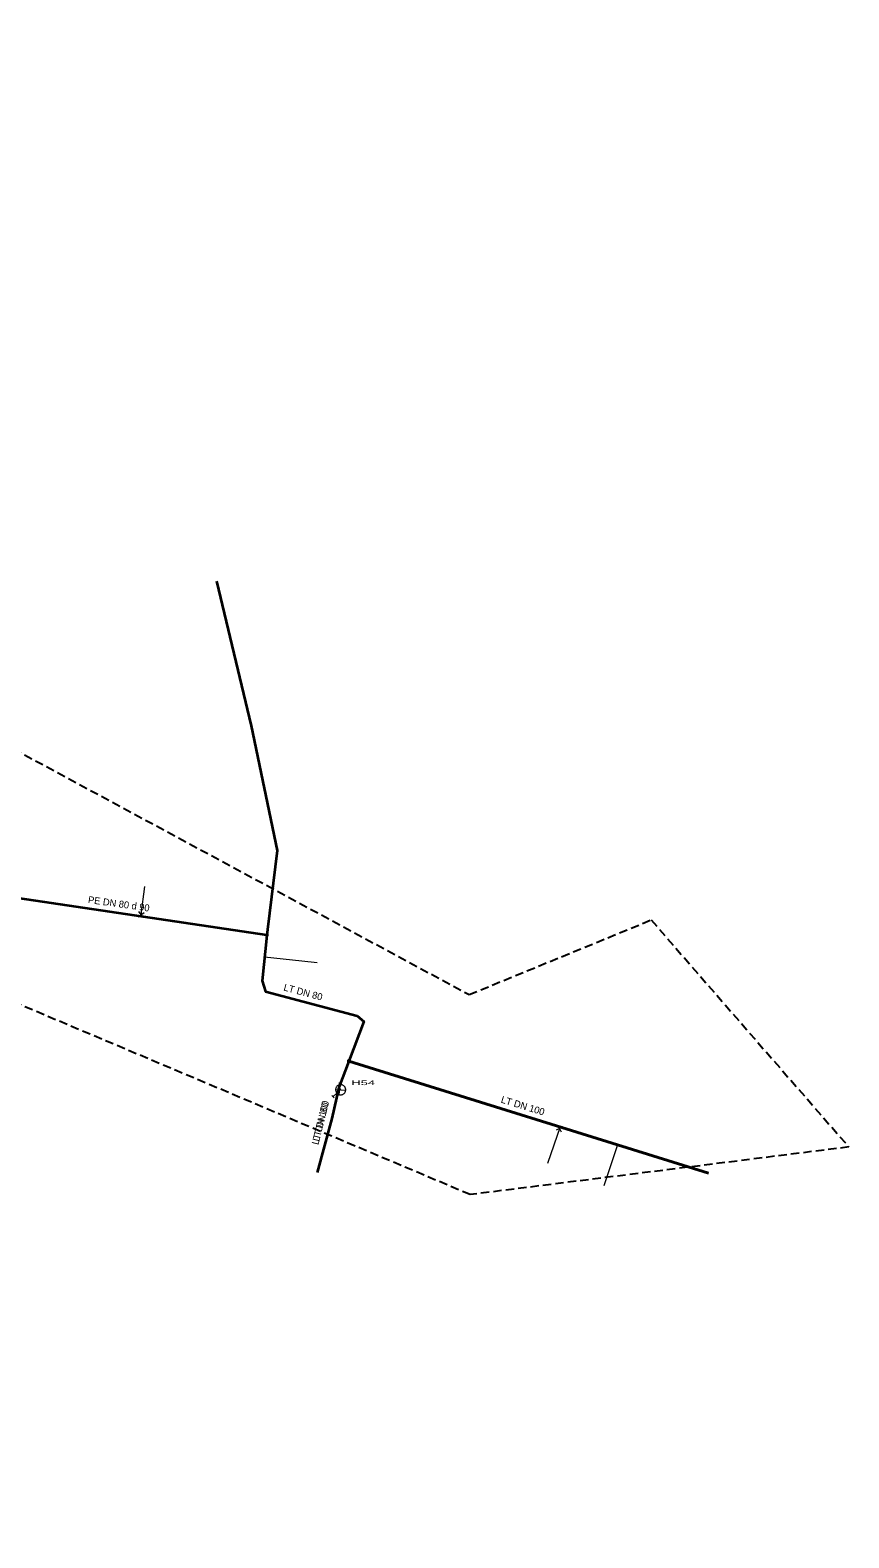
# Model space of a CAD drawing. Extents: x -743677 to -742923, y -1027084 to -1026416.
# Drawn here: x -743064.4 to -742922.9, y -1026822.2 to -1026561.5 of the extents above; entities that cross this region are included whole.
import ezdxf

# ---------------------------------------------------------------- set-up
doc = ezdxf.new("R2010")
doc.units = 0
doc.header["$LTSCALE"] = 0.48
doc.linetypes.add('MEDIUM_DASHED', pattern=[4.5, 3, -1.5])
for name, color, linetype, lineweight in [('15', 7, 'Continuous', 13), ('16', 7, 'Continuous', 35), ('20', 7, 'Continuous', 13), ('59', 7, 'Continuous', 13), ('62', 7, 'MEDIUM_DASHED', 25)]:
    doc.layers.add(name, color=color, linetype=linetype, lineweight=lineweight)
doc.layers.add('17', color=7, linetype='Continuous')

msp = doc.modelspace()

# ---------------------------------------------------------------- linework, layer by layer
at = {"layer": '15'}
for p, q in [((-743045.784, -1026714.867), (-743044.752, -1026714.092)), ((-743044.878, -1026714.998), (-743045.663, -1026713.959)), ((-743011.041, -1026743.526), (-743011.041, -1026745.388)), ((-742972.346, -1026751.186), (-742973.51, -1026751.745)), ((-742973.209, -1026750.881), (-742972.643, -1026752.053))]:
    msp.add_line(p, q, dxfattribs=at)
for points in [[(-743023.291, -1026718.03), (-743023.297, -1026717.978), (-743023.314, -1026717.928), (-743023.343, -1026717.884), (-743023.38, -1026717.847), (-743023.425, -1026717.82), (-743023.475, -1026717.803), (-743023.528, -1026717.799), (-743023.58, -1026717.806), (-743023.629, -1026717.825), (-743023.672, -1026717.854), (-743023.708, -1026717.893), (-743023.734, -1026717.938), (-743023.75, -1026717.989), (-743023.753, -1026718.041), (-743023.745, -1026718.093), (-743023.725, -1026718.142), (-743023.694, -1026718.185), (-743023.655, -1026718.219), (-743023.609, -1026718.245), (-743023.558, -1026718.259), (-743023.505, -1026718.261), (-743023.454, -1026718.251), (-743023.406, -1026718.23), (-743023.363, -1026718.199), (-743023.329, -1026718.158), (-743023.305, -1026718.112), (-743023.293, -1026718.061)], [(-743023.321, -1026718.03), (-743023.327, -1026717.981), (-743023.344, -1026717.935), (-743023.372, -1026717.895), (-743023.409, -1026717.863), (-743023.453, -1026717.841), (-743023.501, -1026717.83), (-743023.55, -1026717.83), (-743023.597, -1026717.843), (-743023.64, -1026717.867), (-743023.676, -1026717.9), (-743023.703, -1026717.941), (-743023.719, -1026717.988), (-743023.723, -1026718.037), (-743023.716, -1026718.085), (-743023.697, -1026718.13), (-743023.667, -1026718.17), (-743023.629, -1026718.201), (-743023.585, -1026718.221), (-743023.537, -1026718.231), (-743023.488, -1026718.229), (-743023.441, -1026718.214), (-743023.398, -1026718.189), (-743023.364, -1026718.155), (-743023.338, -1026718.113), (-743023.324, -1026718.066)], [(-743023.351, -1026718.03), (-743023.357, -1026717.985), (-743023.374, -1026717.943), (-743023.402, -1026717.908), (-743023.438, -1026717.881), (-743023.48, -1026717.864), (-743023.525, -1026717.859), (-743023.57, -1026717.865), (-743023.611, -1026717.884), (-743023.646, -1026717.912), (-743023.673, -1026717.949), (-743023.689, -1026717.991), (-743023.693, -1026718.036), (-743023.686, -1026718.081), (-743023.667, -1026718.122), (-743023.638, -1026718.156), (-743023.601, -1026718.182), (-743023.558, -1026718.198), (-743023.513, -1026718.201), (-743023.468, -1026718.193), (-743023.428, -1026718.173), (-743023.394, -1026718.144), (-743023.368, -1026718.106), (-743023.354, -1026718.063)], [(-743023.381, -1026718.03), (-743023.386, -1026717.989), (-743023.404, -1026717.952), (-743023.431, -1026717.921), (-743023.466, -1026717.9), (-743023.506, -1026717.889), (-743023.547, -1026717.891), (-743023.586, -1026717.904), (-743023.62, -1026717.928), (-743023.645, -1026717.96), (-743023.66, -1026717.998), (-743023.663, -1026718.039), (-743023.655, -1026718.079), (-743023.635, -1026718.115), (-743023.606, -1026718.144), (-743023.569, -1026718.163), (-743023.529, -1026718.171), (-743023.488, -1026718.167), (-743023.45, -1026718.152), (-743023.418, -1026718.126), (-743023.395, -1026718.092), (-743023.382, -1026718.053)], [(-743023.411, -1026718.03), (-743023.416, -1026717.994), (-743023.434, -1026717.962), (-743023.46, -1026717.937), (-743023.494, -1026717.922), (-743023.53, -1026717.919), (-743023.565, -1026717.927), (-743023.596, -1026717.947), (-743023.619, -1026717.975), (-743023.632, -1026718.009), (-743023.632, -1026718.046), (-743023.621, -1026718.081), (-743023.6, -1026718.11), (-743023.57, -1026718.131), (-743023.535, -1026718.141), (-743023.498, -1026718.139), (-743023.464, -1026718.125), (-743023.437, -1026718.102), (-743023.418, -1026718.07), (-743023.411, -1026718.035)], [(-743023.441, -1026718.03), (-743023.446, -1026717.999), (-743023.463, -1026717.973), (-743023.489, -1026717.956), (-743023.519, -1026717.949), (-743023.55, -1026717.953), (-743023.577, -1026717.97), (-743023.595, -1026717.994), (-743023.603, -1026718.025), (-743023.599, -1026718.055), (-743023.584, -1026718.083), (-743023.559, -1026718.102), (-743023.53, -1026718.111), (-743023.499, -1026718.108), (-743023.471, -1026718.094), (-743023.451, -1026718.07), (-743023.441, -1026718.041)], [(-743023.471, -1026718.03), (-743023.476, -1026718.006), (-743023.493, -1026717.988), (-743023.516, -1026717.979), (-743023.54, -1026717.982), (-743023.561, -1026717.996), (-743023.572, -1026718.018), (-743023.572, -1026718.043), (-743023.559, -1026718.064), (-743023.54, -1026718.078), (-743023.515, -1026718.081), (-743023.492, -1026718.072), (-743023.476, -1026718.054)], [(-743023.501, -1026718.03), (-743023.506, -1026718.015), (-743023.521, -1026718.009), (-743023.536, -1026718.013), (-743023.543, -1026718.027), (-743023.539, -1026718.042), (-743023.526, -1026718.051), (-743023.511, -1026718.048), (-743023.501, -1026718.036)], [(-743009.132, -1026739.806), (-743009.138, -1026739.754), (-743009.155, -1026739.704), (-743009.184, -1026739.66), (-743009.221, -1026739.623), (-743009.266, -1026739.596), (-743009.316, -1026739.579), (-743009.369, -1026739.575), (-743009.421, -1026739.582), (-743009.47, -1026739.601), (-743009.513, -1026739.63), (-743009.549, -1026739.669), (-743009.575, -1026739.714), (-743009.591, -1026739.765), (-743009.594, -1026739.817), (-743009.586, -1026739.869), (-743009.566, -1026739.918), (-743009.535, -1026739.961), (-743009.496, -1026739.995), (-743009.45, -1026740.021), (-743009.399, -1026740.035), (-743009.346, -1026740.037), (-743009.295, -1026740.027), (-743009.247, -1026740.006), (-743009.204, -1026739.975), (-743009.17, -1026739.934), (-743009.146, -1026739.888), (-743009.134, -1026739.837)], [(-743009.162, -1026739.806), (-743009.168, -1026739.757), (-743009.185, -1026739.711), (-743009.213, -1026739.671), (-743009.25, -1026739.639), (-743009.294, -1026739.617), (-743009.342, -1026739.606), (-743009.391, -1026739.606), (-743009.438, -1026739.619), (-743009.481, -1026739.643), (-743009.517, -1026739.676), (-743009.544, -1026739.717), (-743009.56, -1026739.764), (-743009.564, -1026739.813), (-743009.557, -1026739.861), (-743009.538, -1026739.906), (-743009.508, -1026739.946), (-743009.47, -1026739.977), (-743009.426, -1026739.997), (-743009.378, -1026740.007), (-743009.329, -1026740.005), (-743009.282, -1026739.99), (-743009.239, -1026739.965), (-743009.205, -1026739.931), (-743009.179, -1026739.889), (-743009.165, -1026739.842)], [(-743009.192, -1026739.806), (-743009.198, -1026739.761), (-743009.215, -1026739.719), (-743009.243, -1026739.684), (-743009.279, -1026739.657), (-743009.321, -1026739.64), (-743009.366, -1026739.635), (-743009.411, -1026739.641), (-743009.452, -1026739.66), (-743009.487, -1026739.688), (-743009.514, -1026739.725), (-743009.53, -1026739.767), (-743009.534, -1026739.812), (-743009.527, -1026739.857), (-743009.508, -1026739.898), (-743009.479, -1026739.932), (-743009.442, -1026739.958), (-743009.399, -1026739.974), (-743009.354, -1026739.977), (-743009.309, -1026739.969), (-743009.269, -1026739.949), (-743009.235, -1026739.92), (-743009.209, -1026739.882), (-743009.195, -1026739.839)], [(-743009.222, -1026739.806), (-743009.227, -1026739.765), (-743009.245, -1026739.728), (-743009.272, -1026739.697), (-743009.307, -1026739.676), (-743009.347, -1026739.665), (-743009.388, -1026739.667), (-743009.427, -1026739.68), (-743009.461, -1026739.704), (-743009.486, -1026739.736), (-743009.501, -1026739.774), (-743009.504, -1026739.815), (-743009.496, -1026739.855), (-743009.476, -1026739.891), (-743009.447, -1026739.92), (-743009.41, -1026739.939), (-743009.37, -1026739.947), (-743009.329, -1026739.943), (-743009.291, -1026739.928), (-743009.259, -1026739.902), (-743009.236, -1026739.868), (-743009.223, -1026739.829)], [(-743009.252, -1026739.806), (-743009.257, -1026739.77), (-743009.275, -1026739.738), (-743009.301, -1026739.713), (-743009.335, -1026739.698), (-743009.371, -1026739.695), (-743009.406, -1026739.703), (-743009.437, -1026739.723), (-743009.46, -1026739.751), (-743009.473, -1026739.785), (-743009.473, -1026739.822), (-743009.462, -1026739.857), (-743009.441, -1026739.886), (-743009.411, -1026739.907), (-743009.376, -1026739.917), (-743009.339, -1026739.915), (-743009.305, -1026739.901), (-743009.278, -1026739.878), (-743009.259, -1026739.846), (-743009.252, -1026739.811)], [(-743009.282, -1026739.806), (-743009.287, -1026739.775), (-743009.304, -1026739.749), (-743009.33, -1026739.732), (-743009.36, -1026739.725), (-743009.391, -1026739.729), (-743009.418, -1026739.746), (-743009.436, -1026739.77), (-743009.444, -1026739.801), (-743009.44, -1026739.831), (-743009.425, -1026739.859), (-743009.401, -1026739.878), (-743009.371, -1026739.887), (-743009.34, -1026739.884), (-743009.312, -1026739.87), (-743009.292, -1026739.846), (-743009.282, -1026739.817)], [(-743009.312, -1026739.806), (-743009.317, -1026739.782), (-743009.334, -1026739.764), (-743009.357, -1026739.755), (-743009.381, -1026739.758), (-743009.402, -1026739.772), (-743009.413, -1026739.794), (-743009.413, -1026739.819), (-743009.401, -1026739.84), (-743009.381, -1026739.854), (-743009.356, -1026739.857), (-743009.333, -1026739.848), (-743009.317, -1026739.83)], [(-743009.342, -1026739.806), (-743009.347, -1026739.791), (-743009.362, -1026739.785), (-743009.377, -1026739.789), (-743009.384, -1026739.803), (-743009.38, -1026739.818), (-743009.367, -1026739.827), (-743009.352, -1026739.824), (-743009.342, -1026739.812)]]:
    msp.add_lwpolyline(points, close=True, dxfattribs=at)
at = {"layer": '16'}
for p, q in [((-743009.363, -1026739.807), (-742947.225, -1026759.197)), ((-742947.225, -1026759.197), (-743009.363, -1026739.807))]:
    msp.add_line(p, q, dxfattribs=at)
for points in [[(-743032.197, -1026656.85), (-743026.25, -1026681.829), (-743021.73, -1026703.39), (-743023.42, -1026717.059), (-743023.522, -1026718.03)], [(-743032.197, -1026656.85), (-743026.25, -1026681.829), (-743021.73, -1026703.39), (-743023.42, -1026717.059), (-743023.522, -1026718.03)], [(-743023.522, -1026718.03), (-743065.021, -1026711.889), (-743069.953, -1026711.159), (-743070.289, -1026711.109), (-743070.292, -1026711.107)], [(-743023.522, -1026718.03), (-743024.359, -1026725.94), (-743023.76, -1026727.78), (-743007.929, -1026731.98), (-743006.739, -1026732.94), (-743009.363, -1026739.807)], [(-743009.363, -1026739.807), (-743011.109, -1026744.379), (-743012.32, -1026749.76), (-743014.8, -1026759.085)], [(-743009.363, -1026739.807), (-743011.109, -1026744.379), (-743012.32, -1026749.76), (-743014.8, -1026759.085)]]:
    msp.add_lwpolyline(points, dxfattribs=at)
at = {"layer": '20'}
for p, q in [((-743011.637, -1026744.716), (-743009.89, -1026744.823)), ((-743011.911, -1026746.144), (-743012.269, -1026745.739)), ((-743011.427, -1026745.356), (-743012.089, -1026745.942))]:
    msp.add_line(p, q, dxfattribs=at)
msp.add_lwpolyline([(-743011.347, -1026744.111), (-743011.411, -1026744.174), (-743011.47, -1026744.244), (-743011.521, -1026744.321), (-743011.563, -1026744.401), (-743011.597, -1026744.487), (-743011.622, -1026744.576), (-743011.636, -1026744.665), (-743011.643, -1026744.757), (-743011.637, -1026744.848), (-743011.624, -1026744.938), (-743011.602, -1026745.028), (-743011.57, -1026745.114), (-743011.53, -1026745.196), (-743011.481, -1026745.273), (-743011.423, -1026745.345), (-743011.359, -1026745.411), (-743011.289, -1026745.469), (-743011.213, -1026745.519), (-743011.13, -1026745.561), (-743011.044, -1026745.595), (-743010.957, -1026745.618), (-743010.867, -1026745.635), (-743010.775, -1026745.64), (-743010.684, -1026745.637), (-743010.593, -1026745.623), (-743010.503, -1026745.6), (-743010.419, -1026745.568), (-743010.336, -1026745.526), (-743010.259, -1026745.477), (-743010.186, -1026745.421), (-743010.123, -1026745.357), (-743010.065, -1026745.287), (-743010.013, -1026745.209), (-743009.971, -1026745.13), (-743009.938, -1026745.044), (-743009.912, -1026744.955), (-743009.898, -1026744.865), (-743009.891, -1026744.773), (-743009.897, -1026744.682), (-743009.91, -1026744.592), (-743009.933, -1026744.503), (-743009.964, -1026744.416), (-743010.006, -1026744.335), (-743010.054, -1026744.257), (-743010.111, -1026744.186), (-743010.175, -1026744.119), (-743010.247, -1026744.063), (-743010.322, -1026744.011), (-743010.404, -1026743.969), (-743010.49, -1026743.936), (-743010.578, -1026743.912), (-743010.667, -1026743.895), (-743010.759, -1026743.891), (-743010.85, -1026743.894), (-743010.942, -1026743.908), (-743011.031, -1026743.931), (-743011.115, -1026743.962), (-743011.198, -1026744.004), (-743011.275, -1026744.053), (-743011.345, -1026744.11)], dxfattribs=at)
at = {"layer": '59'}
for p, q in [((-743011.11, -1026744.38), (-743010.768, -1026744.766)), ((-743011.11, -1026744.38), (-743010.73, -1026744.81)), ((-742972.836, -1026751.205), (-742975.038, -1026757.526)), ((-742962.896, -1026754.304), (-742965.313, -1026761.364))]:
    msp.add_line(p, q, dxfattribs=at)
for points in [[(-743045.296, -1026714.808), (-743045.27, -1026714.48), (-743044.592, -1026709.606)], [(-743023.92, -1026721.78), (-743017.47, -1026722.463), (-743014.853, -1026722.74)]]:
    msp.add_lwpolyline(points, dxfattribs=at)
at = {"layer": '62'}
msp.add_lwpolyline([(-743185.331, -1026452.124), (-743185.314, -1026452.115), (-743122.624, -1026517.483), (-743128.636, -1026561.04), (-743080.591, -1026678.626), (-742988.56, -1026728.316), (-742957.099, -1026715.401), (-742922.946, -1026754.658), (-742988.389, -1026762.896), (-743109.886, -1026711.598), (-743142.114, -1026640.576), (-743238.891, -1026678.985), (-743355.253, -1026751.681), (-743402.763, -1026809.228), (-743453.197, -1026905.826), (-743482.789, -1027084.226), (-743535.862, -1027074.436), (-743492.719, -1026905.289), (-743434.421, -1026787.581), (-743381.806, -1026711.007), (-743250.543, -1026637.895), (-743166.228, -1026600.23)], close=True, dxfattribs=at)

# ---------------------------------------------------------------- texts
at = {"layer": '17'}
for s, rotation, p in [('PE DN 80 d 90 ', 352, (-743054.483, -1026712.465)), ('LT DN 80', 345, (-743020.722, -1026727.579)), ('LT DN 100 ', 76, (-743014.623, -1026754.365)), ('LT DN 80', 76, (-743014.476, -1026753.781)), ('LT DN 100 ', 343, (-742983.171, -1026746.961)), ('LT DN 100 ', 343, (-742983.166, -1026746.968))]:
    msp.add_text(s, height=1.2, rotation=rotation, dxfattribs=at).set_placement(p)
at = {"layer": '20', "width": 2.1}
msp.add_text('H54 ', height=0.8, dxfattribs=at).set_placement((-743008.939, -1026743.963))

doc.saveas('drawing.dxf')
